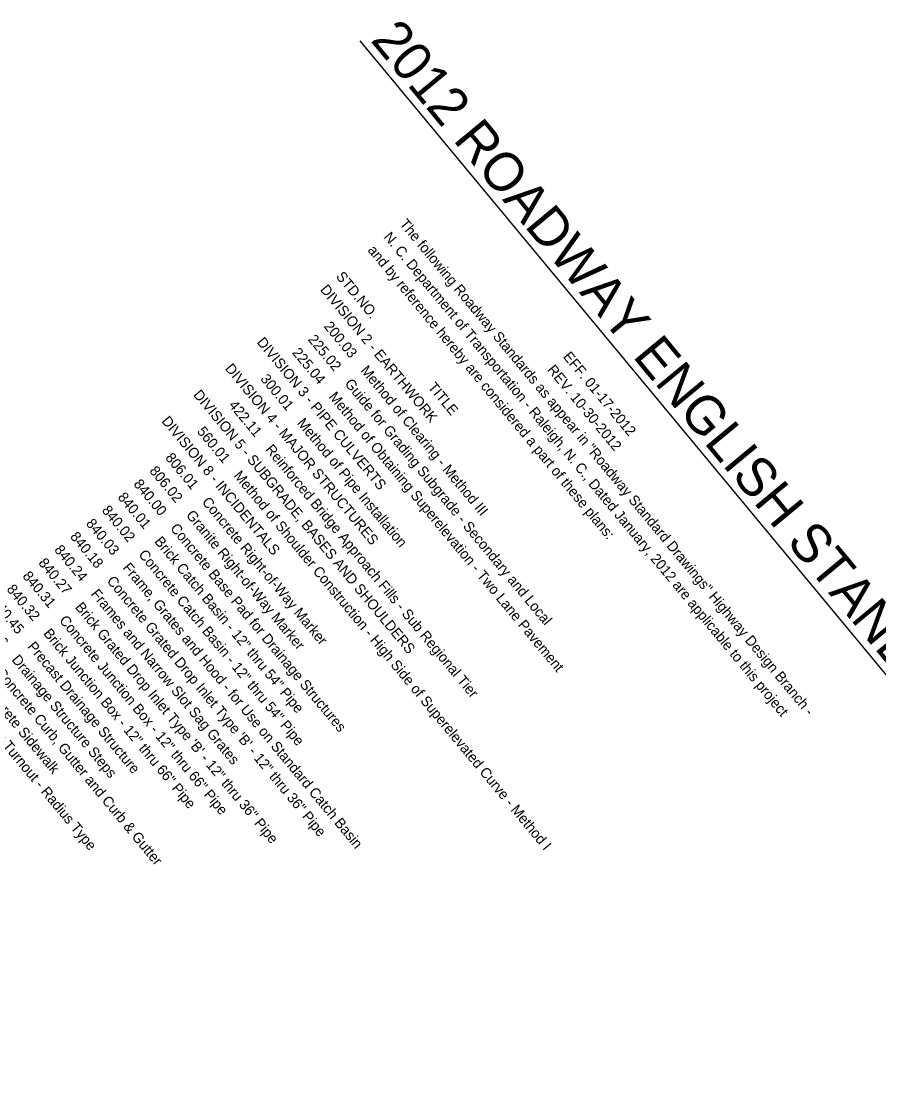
# Model space of a CAD drawing. Extents: x 2054826 to 2060231, y 685508 to 690809.
# Drawn here: x 2056064.9 to 2056397.7, y 686143.1 to 686560.7 of the extents above; entities that cross this region are included whole.
import ezdxf

# ---------------------------------------------------------------- set-up
doc = ezdxf.new("R2010")
doc.units = 0
doc.layers.add('Prop DSN Text', color=7, linetype='Continuous')

msp = doc.modelspace()

# ---------------------------------------------------------------- linework, layer by layer
at = {"layer": 'Prop DSN Text'}
msp.add_line((2056196.26, 686553.18), (2056536.33, 686143.09), dxfattribs=at)

# ---------------------------------------------------------------- texts
for s, height, p in [('2012 ROADWAY ENGLISH STANDARD DRAWINGS', 15, (2056200.16, 686553.28)), ('The following Roadway Standards as appear in "Roadway Standard Drawings" Highway Design Branch -', 4, (2056211.46, 686481.94)), ('N. C. Department of Transportation - Raleigh, N. C., Dated January, 2012 are applicable to this project', 4, (2056205.3, 686476.84)), ('and by reference hereby are considered a part of these plans:', 4, (2056199.14, 686471.73)), ('STD.NO.                       TITLE', 4, (2056186.83, 686461.52)), ('DIVISION 2 - EARTHWORK', 4, (2056180.67, 686456.41)), ('        200.03    Method of Clearing - Method III', 4, (2056174.51, 686451.3)), ('DIVISION 3 - PIPE CULVERTS', 4, (2056156.04, 686435.98)), ('        225.02    Guide for Grading Subgrade - Secondary and Local', 4, (2056168.35, 686446.2)), ('        225.04    Method of Obtaining Superelevation - Two Lane Pavement', 4, (2056162.19, 686441.09)), ('                                                      EFF. 01-17-2012', 4, (2056223.77, 686492.16)), ('DIVISION 4 - MAJOR STRUCTURES', 4, (2056143.72, 686425.77)), ('                                                      REV. 10-30-2012', 4, (2056217.62, 686487.05)), ('        300.01    Method of Pipe Installation ', 4, (2056149.88, 686430.88)), ('DIVISION 5 - SUBGRADE, BASES AND SHOULDERS', 4, (2056131.4, 686415.56)), ('        422.11    Reinforced Bridge Approach Fills - Sub Regional Tier', 4, (2056137.56, 686420.66)), ('DIVISION 8 - INCIDENTALS', 4, (2056119.09, 686405.34)), ('        560.01    Method of Shoulder Construction - High Side of Superelevated Curve - Method I', 4, (2056125.24, 686410.45)), ('        806.01    Concrete Right-of-Way Marker', 4, (2056112.93, 686400.24)), ('        806.02    Granite Right-of-Way Marker', 4, (2056106.77, 686395.13)), ('        840.00    Concrete Base Pad for Drainage Structures', 4, (2056100.61, 686390.02)), ('        840.01    Brick Catch Basin - 12" thru 54" Pipe', 4, (2056094.45, 686384.92)), ('        840.02    Concrete Catch Basin - 12" thru 54" Pipe', 4, (2056088.3, 686379.81)), ('        840.03    Frame, Grates and Hood - for Use on Standard Catch Basin', 4, (2056082.14, 686374.7)), ('        840.18    Concrete Grated Drop Inlet Type \'B\' - 12" thru 36" Pipe', 4, (2056075.98, 686369.6)), ('        840.24    Frames and Narrow Slot Sag Grates', 4, (2056069.82, 686364.49)), ('        840.27    Brick Grated Drop Inlet Type \'B\' - 12" thru 36" Pipe', 4, (2056063.66, 686359.38)), ('        840.31    Concrete Junction Box - 12" thru 66" Pipe', 4, (2056057.51, 686354.28)), ('        840.32    Brick Junction Box - 12" thru 66" Pipe', 4, (2056051.35, 686349.17)), ('        840.45    Precast Drainage Structure', 4, (2056045.19, 686344.07)), ('        840.66    Drainage Structure Steps', 4, (2056039.03, 686338.96)), ('        846.01    Concrete Curb, Gutter and Curb & Gutter', 4, (2056032.87, 686333.85)), ('        848.01    Concrete Sidewalk', 4, (2056026.71, 686328.75)), ('        848.02    Driveway Turnout - Radius Type', 4, (2056020.56, 686323.64))]:
    msp.add_text(s, height=height, rotation=309.6672, dxfattribs=at).set_placement(p)

doc.saveas('drawing.dxf')
